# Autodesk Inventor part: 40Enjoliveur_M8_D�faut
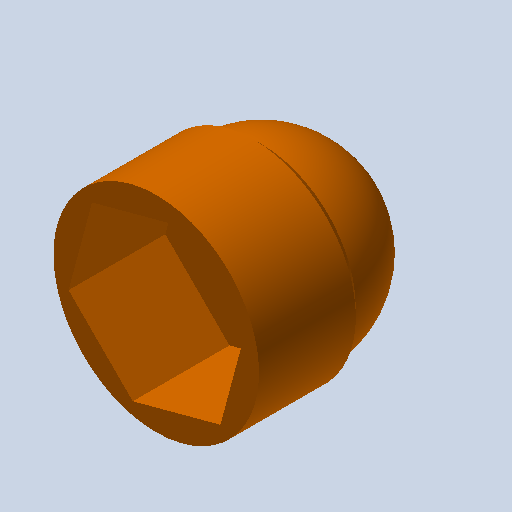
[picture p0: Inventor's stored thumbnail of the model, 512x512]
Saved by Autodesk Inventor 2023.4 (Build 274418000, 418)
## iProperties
Created: 2011-01
Part Number: 40Enjoliveur_M8_D�faut
Document SubType Name: Modeling
Designer: eric
Density: 1 g/cm^3
Mass: 1.78368 g
Surface Area: 14.472 cm^2
Volume: 1.78368 cm^3
Material: Générique
Appearance: 255,128,0_1
Author: eric
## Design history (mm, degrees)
feature "Base1"
node "Corps solides"
node "Corps surfaciques"
node "Solide1"
